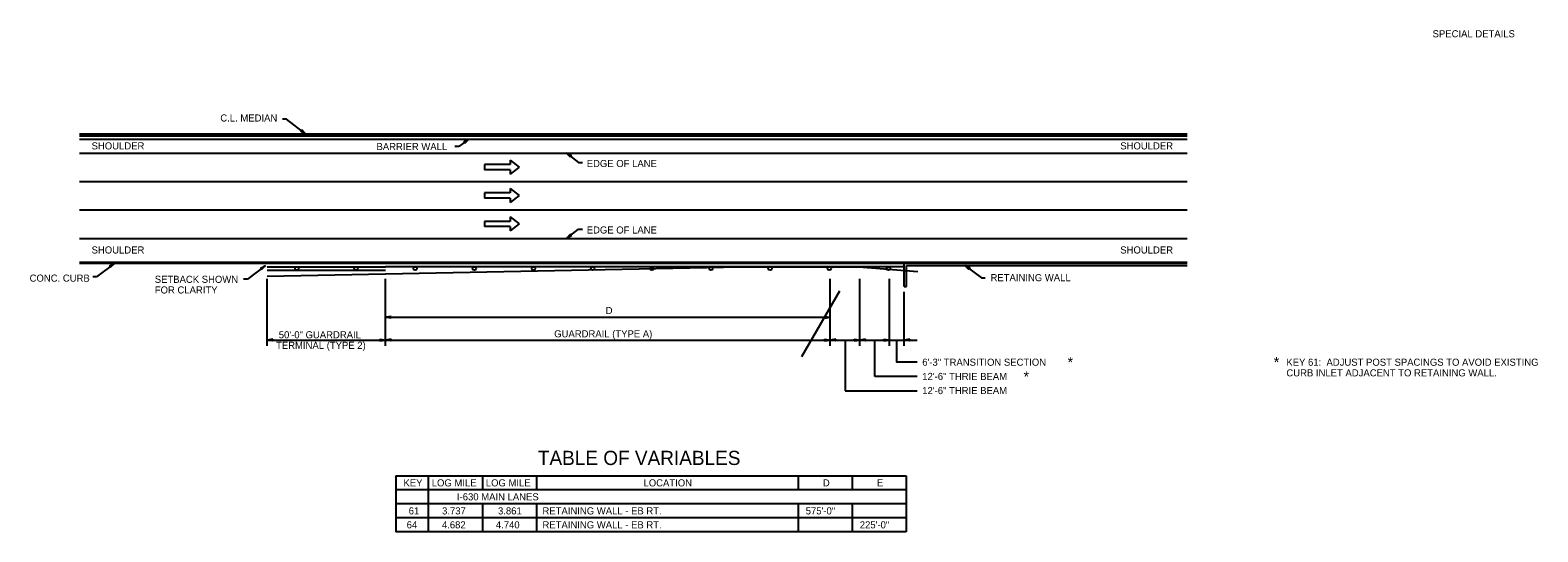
# Model space of a CAD drawing. Extents: x 1373853 to 1374003, y 380191 to 380927.
# Drawn here: x 1373873.1 to 1374000.6, y 380565.8 to 380608.2 of the extents above; entities that cross this region are included whole.
import ezdxf

# ---------------------------------------------------------------- set-up
doc = ezdxf.new("R2010")
doc.units = 0
for name, color, linetype in [('2', 7, 'Continuous'), ('44', 7, 'Continuous'), ('7', 7, 'Continuous'), ('8', 7, 'Continuous'), ('Default', 7, 'Continuous'), ('E_Existing ROW', 7, 'Continuous'), ('G-ANNO-TEXT', 7, 'Continuous'), ('Plan Notes', 7, 'Continuous'), ('R_Proposed Road', 7, 'Continuous')]:
    doc.layers.add(name, color=color, linetype=linetype)

msp = doc.modelspace()

# ---------------------------------------------------------------- linework, layer by layer
at = {"layer": '2'}
for p, q in [((1373894.8, 380600.68), (1373894.48, 380600.68)), ((1373896.42, 380599.45), (1373894.8, 380600.68)), ((1373910.22, 380599), (1373909.37, 380598.36)), ((1373909.37, 380598.36), (1373909.05, 380598.36)), ((1373918.47, 380597.8), (1373919.5, 380597.02)), ((1373919.5, 380597.02), (1373919.82, 380597.02)), ((1373918.47, 380590.6), (1373919.5, 380591.38)), ((1373919.5, 380591.38), (1373919.82, 380591.38)), ((1373878.75, 380587.34), (1373878.43, 380587.34)), ((1373880.29, 380588.5), (1373878.75, 380587.34)), ((1373893.05, 380588.31), (1373891.51, 380587.14)), ((1373952.16, 380588.3), (1373953.55, 380587.26)), ((1373891.51, 380587.14), (1373891.19, 380587.14)), ((1373893.18, 380581.52), (1373893.18, 380587.17)), ((1373903.18, 380581.52), (1373903.18, 380587.17)), ((1373940.78, 380581.52), (1373940.78, 380587.17)), ((1373943.28, 380581.52), (1373943.28, 380587.17)), ((1373945.78, 380581.52), (1373945.78, 380587.17)), ((1373947.03, 380581.52), (1373947.03, 380586.07)), ((1373953.55, 380587.26), (1373953.87, 380587.26)), ((1373903.18, 380583.93), (1373940.78, 380583.93)), ((1373893.18, 380582), (1373903.18, 380582)), ((1373903.18, 380582), (1373940.78, 380582)), ((1373940.78, 380582), (1373943.28, 380582)), ((1373942.03, 380582), (1373942.03, 380577.71)), ((1373943.28, 380582), (1373945.78, 380582)), ((1373944.53, 380578.93), (1373944.53, 380582)), ((1373945.78, 380582), (1373947.03, 380582)), ((1373947.03, 380582), (1373948.11, 380582)), ((1373948.11, 380578.93), (1373944.53, 380578.93)), ((1373942.03, 380577.71), (1373948.11, 380577.71))]:
    msp.add_line(p, q, dxfattribs=at)
msp.add_lwpolyline([(1373948.11, 380580.13), (1373946.4, 380580.13), (1373946.4, 380582)], dxfattribs=at)
at = {"layer": '44'}
for p, q in [((1373877.32, 380588.6), (1373970.94, 380588.6)), ((1373877.32, 380588.5), (1373970.94, 380588.5)), ((1373947.03, 380586.53), (1373947.03, 380588.5)), ((1373947.23, 380588.3), (1373970.94, 380588.3)), ((1373947.23, 380586.53), (1373947.23, 380588.3)), ((1373947.03, 380586.53), (1373947.23, 380586.53))]:
    msp.add_line(p, q, dxfattribs=at)
at = {"layer": '7'}
for p, q in [((1373896, 380599.69), (1373896.08, 380599.8)), ((1373896, 380599.69), (1373896.42, 380599.45)), ((1373896, 380599.69), (1373896.36, 380599.5)), ((1373896.01, 380599.7), (1373896.29, 380599.55)), ((1373896.02, 380599.71), (1373896.23, 380599.6)), ((1373896.03, 380599.74), (1373896.1, 380599.7)), ((1373896.03, 380599.72), (1373896.17, 380599.65)), ((1373896.05, 380599.76), (1373896.17, 380599.65)), ((1373896.05, 380599.75), (1373896.1, 380599.7)), ((1373896.06, 380599.77), (1373896.23, 380599.6)), ((1373896.07, 380599.79), (1373896.36, 380599.5)), ((1373896.07, 380599.78), (1373896.29, 380599.55)), ((1373896.08, 380599.8), (1373896.42, 380599.45)), ((1373909.79, 380598.77), (1373910.22, 380599)), ((1373909.79, 380598.77), (1373909.88, 380598.66)), ((1373909.8, 380598.76), (1373910.15, 380598.96)), ((1373909.8, 380598.75), (1373910.08, 380598.91)), ((1373909.81, 380598.74), (1373910.02, 380598.86)), ((1373909.82, 380598.73), (1373909.96, 380598.81)), ((1373909.82, 380598.72), (1373909.89, 380598.76)), ((1373909.84, 380598.71), (1373909.89, 380598.76)), ((1373909.85, 380598.69), (1373910.02, 380598.86)), ((1373909.85, 380598.7), (1373909.96, 380598.81)), ((1373909.86, 380598.68), (1373910.08, 380598.91)), ((1373909.87, 380598.67), (1373910.15, 380598.96)), ((1373909.88, 380598.66), (1373910.22, 380599)), ((1373918.89, 380597.57), (1373918.47, 380597.8)), ((1373918.81, 380597.46), (1373918.47, 380597.8)), ((1373918.89, 380597.56), (1373918.53, 380597.76)), ((1373918.82, 380597.47), (1373918.53, 380597.76)), ((1373918.82, 380597.48), (1373918.6, 380597.71)), ((1373918.88, 380597.55), (1373918.6, 380597.71)), ((1373918.87, 380597.54), (1373918.66, 380597.66)), ((1373918.83, 380597.49), (1373918.66, 380597.66)), ((1373918.84, 380597.5), (1373918.72, 380597.61)), ((1373918.86, 380597.53), (1373918.72, 380597.61)), ((1373918.84, 380597.51), (1373918.79, 380597.56)), ((1373918.86, 380597.52), (1373918.79, 380597.56)), ((1373918.89, 380597.57), (1373918.81, 380597.46)), ((1373918.81, 380590.95), (1373918.47, 380590.6)), ((1373918.89, 380590.84), (1373918.47, 380590.6)), ((1373918.82, 380590.94), (1373918.53, 380590.65)), ((1373918.89, 380590.84), (1373918.53, 380590.65)), ((1373918.82, 380590.93), (1373918.6, 380590.7)), ((1373918.88, 380590.85), (1373918.6, 380590.7)), ((1373918.83, 380590.92), (1373918.66, 380590.75)), ((1373918.87, 380590.86), (1373918.66, 380590.75)), ((1373918.84, 380590.91), (1373918.72, 380590.8)), ((1373918.86, 380590.87), (1373918.72, 380590.8)), ((1373918.84, 380590.9), (1373918.79, 380590.85)), ((1373918.86, 380590.89), (1373918.79, 380590.85)), ((1373918.89, 380590.84), (1373918.81, 380590.95)), ((1373879.86, 380588.27), (1373880.29, 380588.5)), ((1373879.86, 380588.27), (1373879.95, 380588.16)), ((1373879.87, 380588.26), (1373880.22, 380588.46)), ((1373879.88, 380588.25), (1373880.16, 380588.41)), ((1373879.88, 380588.24), (1373880.09, 380588.36)), ((1373879.89, 380588.23), (1373880.03, 380588.31)), ((1373879.9, 380588.22), (1373879.96, 380588.26)), ((1373879.91, 380588.21), (1373879.96, 380588.26)), ((1373879.92, 380588.2), (1373880.03, 380588.31)), ((1373879.93, 380588.18), (1373880.16, 380588.41)), ((1373879.93, 380588.19), (1373880.09, 380588.36)), ((1373879.94, 380588.17), (1373880.22, 380588.46)), ((1373879.95, 380588.16), (1373880.29, 380588.5)), ((1373892.62, 380588.07), (1373893.05, 380588.31)), ((1373892.62, 380588.07), (1373892.71, 380587.96)), ((1373892.63, 380588.06), (1373892.98, 380588.26)), ((1373892.64, 380588.05), (1373892.92, 380588.21)), ((1373892.64, 380588.04), (1373892.85, 380588.16)), ((1373892.65, 380588.03), (1373892.79, 380588.11)), ((1373892.66, 380588.02), (1373892.72, 380588.06)), ((1373892.67, 380588.01), (1373892.72, 380588.06)), ((1373892.68, 380588), (1373892.79, 380588.11)), ((1373892.69, 380587.98), (1373892.92, 380588.21)), ((1373892.69, 380587.99), (1373892.85, 380588.16)), ((1373892.7, 380587.97), (1373892.98, 380588.26)), ((1373892.71, 380587.96), (1373893.05, 380588.31)), ((1373952.59, 380588.07), (1373952.16, 380588.3)), ((1373952.5, 380587.96), (1373952.16, 380588.3)), ((1373952.58, 380588.06), (1373952.22, 380588.26)), ((1373952.51, 380587.97), (1373952.22, 380588.26)), ((1373952.52, 380587.98), (1373952.29, 380588.21)), ((1373952.57, 380588.05), (1373952.29, 380588.21)), ((1373952.56, 380588.04), (1373952.35, 380588.16)), ((1373952.52, 380587.99), (1373952.35, 380588.16)), ((1373952.53, 380588), (1373952.42, 380588.11)), ((1373952.56, 380588.03), (1373952.42, 380588.11)), ((1373952.54, 380588.01), (1373952.48, 380588.06)), ((1373952.55, 380588.02), (1373952.48, 380588.06)), ((1373952.59, 380588.07), (1373952.5, 380587.96)), ((1373903.65, 380584), (1373903.18, 380583.93)), ((1373903.65, 380583.85), (1373903.18, 380583.93)), ((1373903.65, 380583.99), (1373903.25, 380583.93)), ((1373903.65, 380583.87), (1373903.25, 380583.93)), ((1373903.65, 380583.97), (1373903.34, 380583.93)), ((1373903.65, 380583.88), (1373903.34, 380583.93)), ((1373903.65, 380583.96), (1373903.42, 380583.93)), ((1373903.65, 380583.89), (1373903.42, 380583.93)), ((1373903.65, 380583.95), (1373903.5, 380583.93)), ((1373903.65, 380583.9), (1373903.5, 380583.93)), ((1373903.65, 380583.93), (1373903.58, 380583.93)), ((1373903.65, 380583.91), (1373903.58, 380583.93)), ((1373903.65, 380583.85), (1373903.65, 380584)), ((1373940.3, 380584), (1373940.78, 380583.93)), ((1373940.3, 380584), (1373940.3, 380583.85)), ((1373940.3, 380583.99), (1373940.69, 380583.93)), ((1373940.3, 380583.97), (1373940.61, 380583.93)), ((1373940.3, 380583.96), (1373940.53, 380583.93)), ((1373940.3, 380583.95), (1373940.45, 380583.93)), ((1373940.3, 380583.94), (1373940.37, 380583.93)), ((1373940.3, 380583.85), (1373940.78, 380583.93)), ((1373940.3, 380583.9), (1373940.45, 380583.93)), ((1373940.3, 380583.88), (1373940.61, 380583.93)), ((1373940.3, 380583.87), (1373940.69, 380583.93)), ((1373940.3, 380583.89), (1373940.53, 380583.93)), ((1373940.3, 380583.92), (1373940.37, 380583.93)), ((1373893.65, 380582.07), (1373893.18, 380582)), ((1373893.65, 380581.93), (1373893.18, 380582)), ((1373893.65, 380582.06), (1373893.25, 380582)), ((1373893.65, 380581.94), (1373893.25, 380582)), ((1373893.65, 380582.05), (1373893.34, 380582)), ((1373893.65, 380581.95), (1373893.34, 380582)), ((1373893.65, 380582.04), (1373893.42, 380582)), ((1373893.65, 380581.97), (1373893.42, 380582)), ((1373893.65, 380582.02), (1373893.5, 380582)), ((1373893.65, 380581.98), (1373893.5, 380582)), ((1373893.65, 380582.01), (1373893.58, 380582)), ((1373893.65, 380581.99), (1373893.58, 380582)), ((1373893.65, 380581.93), (1373893.65, 380582.07)), ((1373902.7, 380582.07), (1373903.18, 380582)), ((1373902.7, 380582.07), (1373902.7, 380581.93)), ((1373902.7, 380582.06), (1373903.09, 380582)), ((1373902.7, 380582.05), (1373903.01, 380582)), ((1373902.7, 380582.04), (1373902.93, 380582)), ((1373902.7, 380582.02), (1373902.85, 380582)), ((1373902.7, 380582.01), (1373902.77, 380582)), ((1373902.7, 380581.93), (1373903.18, 380582)), ((1373902.7, 380581.98), (1373902.85, 380582)), ((1373902.7, 380581.95), (1373903.01, 380582)), ((1373902.7, 380581.94), (1373903.09, 380582)), ((1373902.7, 380581.97), (1373902.93, 380582)), ((1373902.7, 380581.99), (1373902.77, 380582)), ((1373903.65, 380582.07), (1373903.18, 380582)), ((1373903.65, 380581.93), (1373903.18, 380582)), ((1373903.65, 380582.06), (1373903.25, 380582)), ((1373903.65, 380581.94), (1373903.25, 380582)), ((1373903.65, 380582.05), (1373903.34, 380582)), ((1373903.65, 380581.95), (1373903.34, 380582)), ((1373903.65, 380582.04), (1373903.42, 380582)), ((1373903.65, 380581.97), (1373903.42, 380582)), ((1373903.65, 380582.02), (1373903.5, 380582)), ((1373903.65, 380581.98), (1373903.5, 380582)), ((1373903.65, 380582.01), (1373903.58, 380582)), ((1373903.65, 380581.99), (1373903.58, 380582)), ((1373903.65, 380581.93), (1373903.65, 380582.07)), ((1373940.3, 380582.07), (1373940.78, 380582)), ((1373940.3, 380581.93), (1373940.3, 380582.07)), ((1373940.3, 380582.06), (1373940.7, 380582)), ((1373940.3, 380582.05), (1373940.61, 380582)), ((1373940.3, 380582.04), (1373940.53, 380582)), ((1373940.3, 380582.02), (1373940.45, 380582)), ((1373940.3, 380582.01), (1373940.37, 380582)), ((1373940.3, 380581.93), (1373940.78, 380582)), ((1373940.3, 380581.98), (1373940.45, 380582)), ((1373940.3, 380581.95), (1373940.61, 380582)), ((1373940.3, 380581.94), (1373940.7, 380582)), ((1373940.3, 380581.97), (1373940.53, 380582)), ((1373940.3, 380581.99), (1373940.37, 380582)), ((1373941.25, 380582.07), (1373940.78, 380582)), ((1373941.25, 380581.93), (1373940.78, 380582)), ((1373941.25, 380582.06), (1373940.85, 380582)), ((1373941.25, 380581.94), (1373940.85, 380582)), ((1373941.25, 380582.05), (1373940.94, 380582)), ((1373941.25, 380581.95), (1373940.94, 380582)), ((1373941.25, 380582.04), (1373941.02, 380582)), ((1373941.25, 380581.97), (1373941.02, 380582)), ((1373941.25, 380582.02), (1373941.1, 380582)), ((1373941.25, 380581.98), (1373941.1, 380582)), ((1373941.25, 380582.01), (1373941.18, 380582)), ((1373941.25, 380581.99), (1373941.18, 380582)), ((1373941.25, 380581.93), (1373941.25, 380582.07)), ((1373942.8, 380582.07), (1373943.28, 380582)), ((1373942.8, 380581.93), (1373942.8, 380582.07)), ((1373942.8, 380582.06), (1373943.2, 380582)), ((1373942.8, 380582.05), (1373943.11, 380582)), ((1373942.8, 380582.04), (1373943.03, 380582)), ((1373942.8, 380582.02), (1373942.95, 380582)), ((1373942.8, 380582.01), (1373942.87, 380582)), ((1373942.8, 380581.93), (1373943.28, 380582)), ((1373942.8, 380581.98), (1373942.95, 380582)), ((1373942.8, 380581.95), (1373943.11, 380582)), ((1373942.8, 380581.94), (1373943.2, 380582)), ((1373942.8, 380581.97), (1373943.03, 380582)), ((1373942.8, 380581.99), (1373942.87, 380582)), ((1373943.75, 380582.07), (1373943.28, 380582)), ((1373943.75, 380581.93), (1373943.28, 380582)), ((1373943.75, 380582.06), (1373943.35, 380582)), ((1373943.75, 380581.94), (1373943.35, 380582)), ((1373943.75, 380582.05), (1373943.44, 380582)), ((1373943.75, 380581.95), (1373943.44, 380582)), ((1373943.75, 380582.04), (1373943.52, 380582)), ((1373943.75, 380581.97), (1373943.52, 380582)), ((1373943.75, 380582.02), (1373943.6, 380582)), ((1373943.75, 380581.98), (1373943.6, 380582)), ((1373943.75, 380582.01), (1373943.68, 380582)), ((1373943.75, 380581.99), (1373943.68, 380582)), ((1373943.75, 380581.93), (1373943.75, 380582.07)), ((1373945.3, 380582.07), (1373945.78, 380582)), ((1373945.3, 380581.93), (1373945.3, 380582.07)), ((1373945.3, 380582.06), (1373945.7, 380582)), ((1373945.3, 380582.05), (1373945.61, 380582)), ((1373945.3, 380582.04), (1373945.53, 380582)), ((1373945.3, 380582.02), (1373945.45, 380582)), ((1373945.3, 380582.01), (1373945.37, 380582)), ((1373945.3, 380581.93), (1373945.78, 380582)), ((1373945.3, 380581.98), (1373945.45, 380582)), ((1373945.3, 380581.95), (1373945.61, 380582)), ((1373945.3, 380581.94), (1373945.7, 380582)), ((1373945.3, 380581.97), (1373945.53, 380582)), ((1373945.3, 380581.99), (1373945.37, 380582)), ((1373947.5, 380582.07), (1373947.03, 380582)), ((1373947.5, 380581.93), (1373947.03, 380582)), ((1373947.5, 380582.06), (1373947.1, 380582)), ((1373947.5, 380581.94), (1373947.1, 380582)), ((1373947.5, 380582.05), (1373947.19, 380582)), ((1373947.5, 380581.95), (1373947.19, 380582)), ((1373947.5, 380582.04), (1373947.27, 380582)), ((1373947.5, 380581.97), (1373947.27, 380582)), ((1373947.5, 380582.02), (1373947.35, 380582)), ((1373947.5, 380581.98), (1373947.35, 380582)), ((1373947.5, 380582.01), (1373947.43, 380582)), ((1373947.5, 380581.99), (1373947.43, 380582)), ((1373947.5, 380581.93), (1373947.5, 380582.07))]:
    msp.add_line(p, q, dxfattribs=at)
at = {"layer": 'Default'}
for p, q in [((1373913.71, 380596.84), (1373911.55, 380596.84)), ((1373911.55, 380596.84), (1373911.55, 380596.4)), ((1373913.71, 380596.4), (1373911.55, 380596.4)), ((1373913.71, 380597.21), (1373913.71, 380596.84)), ((1373913.71, 380597.21), (1373914.47, 380596.62)), ((1373914.47, 380596.62), (1373913.71, 380596.03)), ((1373913.71, 380596.4), (1373913.71, 380596.03)), ((1373913.71, 380594.44), (1373911.55, 380594.44)), ((1373911.55, 380594.44), (1373911.55, 380594)), ((1373913.71, 380594), (1373911.55, 380594)), ((1373913.71, 380594.81), (1373913.71, 380594.44)), ((1373913.71, 380594.81), (1373914.47, 380594.22)), ((1373914.47, 380594.22), (1373913.71, 380593.63)), ((1373913.71, 380594), (1373913.71, 380593.63)), ((1373913.71, 380592.41), (1373913.71, 380592.04)), ((1373913.71, 380592.41), (1373914.47, 380591.82)), ((1373913.71, 380592.04), (1373911.55, 380592.04)), ((1373911.55, 380592.04), (1373911.55, 380591.6)), ((1373913.71, 380591.6), (1373911.55, 380591.6)), ((1373914.47, 380591.82), (1373913.71, 380591.23)), ((1373913.71, 380591.6), (1373913.71, 380591.23))]:
    msp.add_line(p, q, dxfattribs=at)
at = {"layer": 'E_Existing ROW'}
msp.add_lwpolyline([(1373938.38, 380580.62), (1373941.58, 380586.16)], dxfattribs=at)
msp.add_lwpolyline([(1373938.38, 380580.62), (1373941.58, 380586.16)], dxfattribs=at)
at = {"layer": 'Plan Notes'}
for p, q in [((1373904.05, 380570.53), (1373947.19, 380570.53)), ((1373904.05, 380570.53), (1373904.05, 380565.79)), ((1373906.8, 380570.53), (1373906.8, 380565.79)), ((1373911.37, 380570.53), (1373911.37, 380569.34)), ((1373915.94, 380570.53), (1373915.94, 380569.34)), ((1373938.05, 380570.53), (1373938.05, 380569.34)), ((1373942.62, 380570.53), (1373942.62, 380569.34)), ((1373947.19, 380570.53), (1373947.19, 380565.79)), ((1373911.37, 380568.16), (1373911.37, 380565.79)), ((1373915.94, 380568.16), (1373915.94, 380565.79)), ((1373938.05, 380568.16), (1373938.05, 380565.79)), ((1373942.62, 380568.16), (1373942.62, 380565.79))]:
    msp.add_line(p, q, dxfattribs=at)
for points in [[(1373947.19, 380569.34), (1373904.05, 380569.34)], [(1373947.19, 380568.16), (1373904.05, 380568.16)], [(1373947.19, 380566.97), (1373904.05, 380566.97)], [(1373947.19, 380565.79), (1373904.05, 380565.79)]]:
    msp.add_lwpolyline(points, dxfattribs=at)
at = {"layer": 'R_Proposed Road'}
for p, q in [((1373877.32, 380599.45), (1373970.94, 380599.45)), ((1373877.32, 380599.27), (1373970.94, 380599.27)), ((1373877.32, 380599), (1373970.94, 380599)), ((1373877.32, 380597.8), (1373970.94, 380597.8)), ((1373877.32, 380595.4), (1373970.94, 380595.4)), ((1373877.32, 380593), (1373970.94, 380593)), ((1373877.32, 380590.6), (1373970.94, 380590.6)), ((1373893.17, 380588.2), (1373903.18, 380588.2)), ((1373893.17, 380587.9), (1373903.18, 380587.91)), ((1373893.18, 380587.4), (1373933.18, 380588.2)), ((1373933.18, 380588.2), (1373943.18, 380588.2)), ((1373943.18, 380588.2), (1373948.18, 380587.8))]:
    msp.add_line(p, q, dxfattribs=at)
for points in [[(1373905.69, 380588.2), (1373903.18, 380588.2)], [(1373908.19, 380588.2), (1373905.69, 380588.2)], [(1373910.69, 380588.2), (1373908.19, 380588.2)], [(1373915.69, 380588.2), (1373910.69, 380588.2)], [(1373918.19, 380588.2), (1373915.69, 380588.2)], [(1373920.69, 380588.2), (1373918.19, 380588.2)], [(1373925.69, 380588.2), (1373920.69, 380588.2)], [(1373928.19, 380588.2), (1373925.69, 380588.2)], [(1373930.69, 380588.2), (1373928.19, 380588.2)], [(1373933.18, 380588.2), (1373930.69, 380588.2)], [(1373935.69, 380588.2), (1373933.18, 380588.2)], [(1373938.19, 380588.2), (1373935.69, 380588.2)], [(1373940.69, 380588.2), (1373938.19, 380588.2)], [(1373943.19, 380588.2), (1373940.69, 380588.2)], [(1373945.69, 380588.2), (1373943.19, 380588.2)], [(1373947.03, 380588.2), (1373945.69, 380588.2)]]:
    msp.add_lwpolyline(points, dxfattribs=at)
for centre in [(1373895.69, 380588.05), (1373900.69, 380588.05), (1373905.69, 380588.05), (1373910.69, 380588.05), (1373915.69, 380588.05), (1373920.69, 380588.05), (1373925.69, 380588.05), (1373930.69, 380588.05), (1373935.69, 380588.05), (1373940.69, 380588.05), (1373945.69, 380588.05)]:
    msp.add_circle(centre, 0.15, dxfattribs=at)

# ---------------------------------------------------------------- texts
at = {"layer": '2'}
for s, height, rotation, p in [('C.L. MEDIAN', 0.6, 0, (1373889.22, 380600.48)), ('SHOULDER', 0.6, 0, (1373878.34, 380598.12)), ('BARRIER WALL', 0.6, 360, (1373902.42, 380598.06)), ('SHOULDER', 0.6, 0, (1373965.29, 380598.12)), ('EDGE OF LANE', 0.6, 0, (1373920.19, 380596.63)), ('EDGE OF LANE', 0.6, 0, (1373920.19, 380591.01)), ('SHOULDER', 0.6, 0, (1373878.34, 380589.32)), ('SHOULDER', 0.6, 0, (1373965.29, 380589.32)), ('CONC. CURB', 0.6, 360, (1373873.1, 380586.94)), ('SETBACK SHOWN', 0.6, 360, (1373883.68, 380586.84)), ('RETAINING WALL', 0.6, 0, (1373954.32, 380586.98)), ('FOR CLARITY', 0.6, 360, (1373883.68, 380585.94)), ('D', 0.6, 0, (1373921.79, 380584.2)), ('50\'-0" GUARDRAIL', 0.6, 0, (1373894.16, 380582.15)), ('GUARDRAIL (TYPE A)', 0.6, 0, (1373917.44, 380582.23)), ('TERMINAL (TYPE 2)', 0.6, 0, (1373893.93, 380581.26)), ('6\'-3" TRANSITION SECTION', 0.6, 0, (1373948.55, 380579.83)), ('*', 0.9, 0, (1373960.83, 380579.67)), ('*', 0.9, 0, (1373978.26, 380579.68)), ('KEY 61:  ADJUST POST SPACINGS TO AVOID EXISTING', 0.6, 0, (1373979.33, 380579.83)), ('12\'-6" THRIE BEAM', 0.6, 0, (1373948.55, 380578.63)), ('*', 0.9, 0, (1373957.11, 380578.46)), ('CURB INLET ADJACENT TO RETAINING WALL.', 0.6, 0, (1373979.33, 380578.93)), ('12\'-6" THRIE BEAM', 0.6, 0, (1373948.55, 380577.43)), ('KEY', 0.6, 0, (1373904.7, 380569.63)), ('LOG MILE', 0.6, 0, (1373907.09, 380569.63)), ('LOG MILE', 0.6, 0, (1373911.66, 380569.63)), ('LOCATION', 0.6, 0, (1373924.99, 380569.63)), ('D', 0.6, 0, (1373940.15, 380569.63)), ('E', 0.6, 0, (1373944.72, 380569.63)), ('I-630 MAIN LANES', 0.6, 0, (1373909.22, 380568.45)), ('61', 0.6, 0, (1373905.14, 380567.26)), ('3.737', 0.6, 0, (1373907.96, 380567.26)), ('3.861', 0.6, 0, (1373912.69, 380567.26)), ('RETAINING WALL - EB RT.', 0.6, 0, (1373916.45, 380567.26)), ('575\'-0"', 0.6, 0, (1373938.7, 380567.26)), ('64', 0.6, 0, (1373904.97, 380566.08)), ('4.682', 0.6, 0, (1373907.95, 380566.08)), ('4.740', 0.6, 0, (1373912.51, 380566.08)), ('RETAINING WALL - EB RT.', 0.6, 0, (1373916.45, 380566.08)), ('225\'-0"', 0.6, 0, (1373943.27, 380566.08))]:
    msp.add_text(s, height=height, rotation=rotation, dxfattribs=at).set_placement(p)
at = {"layer": '8'}
msp.add_text('TABLE OF VARIABLES', height=1.2, rotation=0, dxfattribs=at).set_placement((1373916.06, 380571.44))
at = {"layer": 'G-ANNO-TEXT'}
msp.add_text('SPECIAL DETAILS', height=0.6, dxfattribs=at).set_placement((1373991.69, 380607.6))

doc.saveas('drawing.dxf')
